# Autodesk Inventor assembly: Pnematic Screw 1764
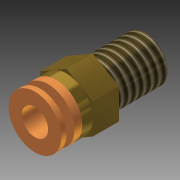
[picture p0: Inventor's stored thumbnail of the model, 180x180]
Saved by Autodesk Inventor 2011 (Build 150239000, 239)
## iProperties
Created: 2010-02
Part Number: Pnematic Screw 1764
Document SubType Name: Assembly
Designer: clee1
Author: clee1
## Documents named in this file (3)
- R:\CAD Archives\Pneumatics\Pnewmatics T Intersection 1764\Pnewmatic Screw 1764\Pneumatic Screw 1764.iam
- R:\CAD Archives\Pneumatics\Pnewmatics T Intersection 1764\Pnewmatic Screw 1764\Pneumatic Screw Part 1 1764.ipt
- R:\CAD Archives\Pneumatics\Pnewmatics T Intersection 1764\Pnewmatic Screw 1764\Pneumatic Screw Part 2 1764.ipt
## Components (2 placed, 2 different names)
1. Pneumatic Screw Part 1 1764:1 — Insert:1
2. Pneumatic Screw Part 2 1764:1 — Insert:1
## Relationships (1: Insert 1)
- Insert:1: Pneumatic Screw Part 1 1764:1 ↔ Pneumatic Screw Part 2 1764:1
